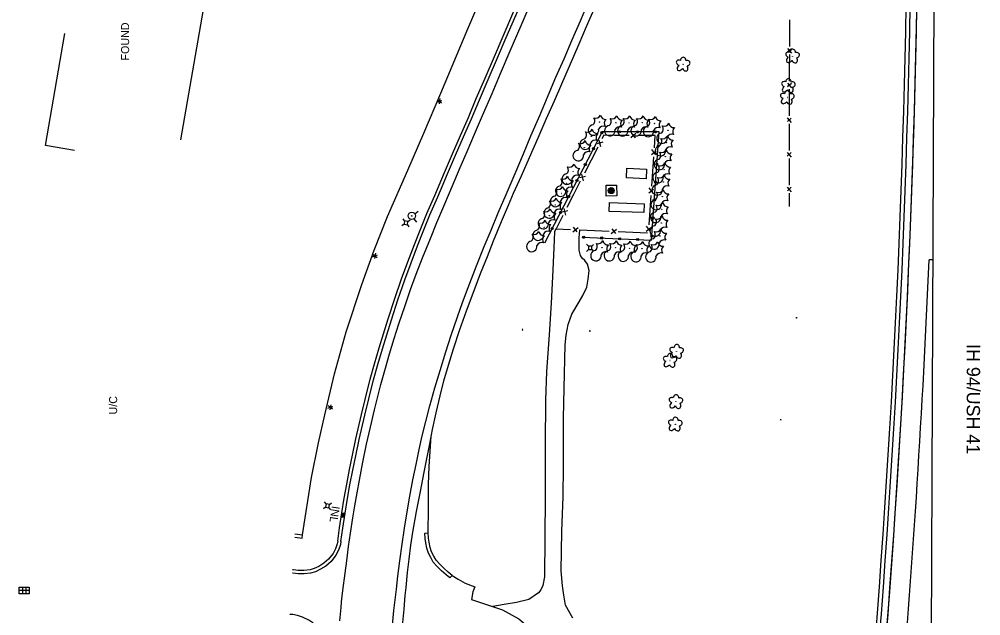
# Model space of a CAD drawing. Extents: x 588843 to 2552415, y 180129 to 269402.
# Drawn here: x 593269 to 593990, y 186692 to 187140 of the extents above; entities that cross this region are included whole.
import ezdxf

# ---------------------------------------------------------------- set-up
doc = ezdxf.new("R2010")
doc.units = 0
for name, color, linetype in [('Default', 7, 'Continuous'), ('E_AREA', 7, 'Continuous'), ('E_BMGRD_P', 7, 'Continuous'), ('E_DRN', 7, 'Continuous'), ('E_DRN_Text', 7, 'Continuous'), ('E_DWY', 7, 'Continuous'), ('E_FEN_P', 7, 'Continuous'), ('E_LAND_Vegetation', 7, 'Continuous'), ('E_LTG', 7, 'Continuous'), ('E_MISCPROP', 7, 'Continuous'), ('E_RDWY', 7, 'Continuous'), ('E_RDWY_C_and_G', 7, 'Continuous'), ('E_RDWY_Gravel', 7, 'Continuous'), ('E_RDWY_Text', 7, 'Continuous'), ('E_UTL_AG_Bold', 7, 'Continuous'), ('E_UTL_WHydrant', 7, 'Continuous'), ('Level 12', 7, 'Continuous'), ('Level 17', 7, 'Continuous'), ('P_ALI_100', 7, 'Continuous'), ('P_RDWY_PavtEdge', 7, 'Continuous'), ('P_RDWY_ShldAgg', 7, 'Continuous'), ('P_RDWY_ShldPaved', 7, 'Continuous')]:
    doc.layers.add(name, color=color, linetype=linetype)

# ---------------------------------------------------------------- blocks, each defined once
blk = doc.blocks.new('CULV2')
at = {"layer": 'E_DRN'}
blk.add_arc((20, 15), 24.6, 216.8699, 323.1301, dxfattribs=at)
blk = doc.blocks.new('DTRE')
at = {"layer": 'Default'}
blk.add_circle((-0.2, 0), 0.183, dxfattribs=at)
for centre, major_axis, ratio in [((-5.9, 0.2), (4.93, -0.12), 0.832022), ((-1.9, 5.3), (1.36, -4.98), 0.782863), ((4.1, 2.7), (-5.27, -2.93), 0.691916), ((-2.5, -5.2), (1.8, 4.86), 0.716896), ((3.5, -3.7), (-5.01, 4.58), 0.560249)]:
    blk.add_ellipse(centre, major_axis=major_axis, ratio=ratio, start_param=1.570796, end_param=4.712389, dxfattribs=at)
blk = doc.blocks.new('POLE')
at = {"layer": 'Default'}
for radius in [4.46, 3.35, 2.23, 1.12]:
    blk.add_circle((0, 0), radius, dxfattribs=at)
blk = doc.blocks.new('PED')
at = {"layer": 'Default'}
for p, q in [((-2.5, 2.5), (-5.3, 5.3)), ((2.5, 2.5), (5.3, 5.3)), ((-2.5, -2.5), (-5.3, -5.3)), ((2.5, -2.5), (5.3, -5.3))]:
    blk.add_line(p, q, dxfattribs=at)
blk.add_lwpolyline([(-2.5, -2.5), (2.5, -2.5), (2.5, 2.5), (-2.5, 2.5)], close=True, dxfattribs=at)
blk = doc.blocks.new('CTRE')
at = {"layer": 'Default'}
blk.add_circle((0, 0), 0.223, dxfattribs=at)
for centre, start, end in [((-12, 9), 280.2067, 5.9716), ((-13.8, -5.9), 340.2113, 65.9762), ((1.8, 14.9), 220.2113, 305.9762), ((13.8, 5.9), 160.2113, 245.9762), ((-1.8, -14.9), 40.2113, 125.9762), ((12, -9), 185.9272, 100.2511)]:
    blk.add_arc(centre, 7.87, start, end, dxfattribs=at)
blk = doc.blocks.new('INLO')
at = {"layer": 'E_DRN'}
for p, q in [((2, -4), (2, 0)), ((4, -4), (4, 0)), ((6, -2), (0, -2))]:
    blk.add_line(p, q, dxfattribs=at)
blk.add_lwpolyline([(0, -4), (6, -4), (6, 0), (0, 0), (0, -4)], close=True, dxfattribs=at)
blk = doc.blocks.new('INLT_13')
at = {"layer": 'E_DRN_Text'}
blk.add_text('INL', height=12, dxfattribs=at).set_placement((-11, -6))
blk = doc.blocks.new('LPOL')
at = {"layer": 'Default'}
for p, q in [((-4, 0), (-1.5, 0)), ((-0.7, 1.3), (-2, 3.5)), ((0.7, 1.3), (2, 3.5)), ((1.5, 0), (4, 0)), ((-2, -3.5), (-0.7, -1.3)), ((2, -3.5), (0.7, -1.3))]:
    blk.add_line(p, q, dxfattribs=at)
for radius in [1.5, 1.5, 1.5, 0.125]:
    blk.add_circle((0, 0), radius, dxfattribs=at)
blk = doc.blocks.new('HYD')
at = {"layer": 'Default'}
for p, q in [((-3.8, 3.8), (-8.3, 8.3)), ((3.8, 3.8), (8.3, 8.3))]:
    blk.add_line(p, q, dxfattribs=at)
for radius in [5.48, 0.42]:
    blk.add_circle((0, 0), radius, dxfattribs=at)

msp = doc.modelspace()

# ---------------------------------------------------------------- linework, layer by layer
at = {"layer": 'E_AREA'}
for points in [[(593724.51, 187027.99), (593739.18, 187027.36), (593738.87, 187020.21), (593724.2, 187020.84), (593724.51, 187027.99)], [(593716.89, 187007.31), (593708.97, 187007.19), (593708.84, 187015.31), (593716.76, 187015.43), (593716.89, 187007.31)], [(593711.42, 187002.24), (593737.36, 187001.29), (593737.12, 186994.74), (593711.18, 186995.69), (593711.42, 187002.24)]]:
    msp.add_lwpolyline(points, close=True, dxfattribs=at)
at = {"layer": 'E_BMGRD_P'}
msp.add_lwpolyline([(593690.97, 186976.29), (593742.88, 186974.07), (593748.63, 187055.26), (593705.99, 187055.31), (593662.75, 186971.82)], dxfattribs=at)
for centre, radius in [((593718.85, 187055.29), 0.786), ((593732.35, 187055.27), 0.786), ((593745.85, 187055.26), 0.786), ((593705.69, 187054.74), 0.786), ((593705.69, 187054.74), 0.396), ((593718.85, 187055.29), 0.396), ((593732.35, 187055.27), 0.396), ((593745.85, 187055.26), 0.396), ((593699.49, 187042.75), 0.786), ((593699.49, 187042.75), 0.396), ((593747.87, 187044.56), 0.786), ((593747.87, 187044.56), 0.396), ((593693.28, 187030.76), 0.786), ((593693.28, 187030.76), 0.396), ((593746.92, 187031.1), 0.786), ((593746.92, 187031.1), 0.396), ((593687.07, 187018.78), 0.786), ((593687.07, 187018.78), 0.396), ((593745.97, 187017.63), 0.786), ((593745.97, 187017.63), 0.396), ((593680.86, 187006.79), 0.786), ((593680.86, 187006.79), 0.396), ((593745.01, 187004.16), 0.786), ((593745.01, 187004.16), 0.396), ((593674.65, 186994.8), 0.786), ((593674.65, 186994.8), 0.396), ((593744.06, 186990.69), 0.786), ((593744.06, 186990.69), 0.396), ((593668.44, 186982.81), 0.786), ((593668.44, 186982.81), 0.396), ((593692.09, 186976.25), 0.786), ((593692.09, 186976.25), 0.396), ((593743.11, 186977.23), 0.786), ((593743.11, 186977.23), 0.396), ((593705.58, 186975.67), 0.786), ((593705.58, 186975.67), 0.396), ((593719.07, 186975.09), 0.786), ((593719.07, 186975.09), 0.396), ((593732.56, 186974.51), 0.786), ((593732.56, 186974.51), 0.396)]:
    msp.add_circle(centre, radius, dxfattribs=at)
at = {"layer": 'E_DRN'}
for p, q in [((593268.89, 186708.85), (593268.89, 186713.85)), ((593268.89, 186713.85), (593276.39, 186713.85)), ((593276.39, 186711.35), (593268.89, 186711.35)), ((593271.39, 186713.85), (593271.39, 186708.85)), ((593273.89, 186713.85), (593273.89, 186708.85)), ((593276.39, 186713.85), (593276.39, 186708.85)), ((593276.39, 186708.85), (593268.89, 186708.85)), ((593272.64, 186708.85), (593272.64, 186708.85))]:
    msp.add_line(p, q, dxfattribs=at)
at = {"layer": 'E_DWY'}
for points in [[(593480.89, 186750.48), (593481.26, 186752.95), (593488.04, 186796.08), (593493.2, 186821.94), (593498.06, 186843.12), (593505.32, 186873.85), (593513.98, 186905.19), (593525.62, 186940.74), (593534.91, 186966.59), (593544.98, 186991.81), (593560.19, 187026.68), (593572.33, 187054.22), (593584.92, 187084.41), (593605.1, 187132.52), (593619.1, 187165.67)], [(593671.3, 186982.53), (593670.29, 186980.24), (593670.03, 186974.37), (593668.98, 186951.69), (593667.75, 186926.78), (593666.08, 186902.94), (593664.08, 186875.44), (593663.42, 186854.07), (593663.11, 186820.89), (593663.28, 186781.57), (593662.96, 186750.8), (593662.63, 186721.59), (593661.42, 186714.93), (593660.04, 186711.76), (593658.18, 186709.48), (593650.92, 186704.51), (593641.7, 186702.39), (593632.52, 186700.81), (593623.84, 186699.16)], [(593683.95, 186690.5), (593678.43, 186700.33), (593677.09, 186707.72), (593676.17, 186714.68), (593675.27, 186726.01), (593675.6, 186755.5), (593676.58, 186781.7), (593676.98, 186804.25), (593677.06, 186840.47), (593677.5, 186862.94), (593678.14, 186895.56), (593678.94, 186902.73), (593680.32, 186910.85), (593683.25, 186918.58), (593688.64, 186927.79), (593691.41, 186932.67), (593694.35, 186938.73), (593695.44, 186944.9), (593696.14, 186951.4), (593694.93, 186956.12), (593692.89, 186958.9), (593691, 186960.54), (593689.58, 186962.53), (593688.71, 186966.53), (593688.65, 186975.78), (593689.13, 186981.75)], [(593575.57, 186754.43), (593575.82, 186772.99), (593575.66, 186790.68), (593576.23, 186804.33), (593577.84, 186826.93)], [(593475.59, 186753.8), (593481.26, 186752.95)], [(593573.07, 186754.32), (593575.57, 186754.43)], [(593591.77, 186720.72), (593588.92, 186723.07), (593585.41, 186726.13), (593582.04, 186729.59), (593579.34, 186732.61), (593577.39, 186735.96), (593575.77, 186739.33), (593574.49, 186742.97), (593573.71, 186747.05), (593573.25, 186750.28), (593573.07, 186754.32)], [(593593.36, 186722.65), (593590.53, 186724.97), (593587.13, 186727.94), (593583.87, 186731.29), (593581.37, 186734.09), (593579.6, 186737.14), (593578.08, 186740.29), (593576.91, 186743.62), (593576.17, 186747.46), (593575.74, 186750.51), (593575.57, 186754.43)], [(593510.11, 186747.96), (593509.65, 186745.72), (593508.26, 186741.54), (593506.3, 186737.71), (593502.67, 186733.03), (593498.74, 186729.65), (593494.81, 186727.16), (593490.91, 186725.34), (593487.38, 186724.34), (593482.43, 186723.86), (593477.94, 186723.88), (593474.12, 186724.29), (593473.71, 186724.36)], [(593507.63, 186748.29), (593507.23, 186746.37), (593505.95, 186742.51), (593504.18, 186739.06), (593500.85, 186734.76), (593497.25, 186731.66), (593493.61, 186729.36), (593490.04, 186727.69), (593486.92, 186726.81), (593482.31, 186726.36), (593478.08, 186726.38), (593474.44, 186726.77), (593473.87, 186726.86)], [(593475.43, 186751.3), (593480.89, 186750.48)], [(593591.77, 186720.72), (593593.36, 186722.65), (593597.85, 186719.78), (593603.23, 186716.86), (593610.4, 186714.07), (593608.97, 186710.3), (593607.96, 186704.52), (593631.13, 186696.7), (593643.55, 186689.9), (593656.66, 186678.88), (593667.04, 186668.23), (593675.78, 186655.81), (593681.53, 186644.73), (593686.85, 186630.53), (593689.52, 186618.63), (593690.53, 186605.83), (593692.03, 186587.19), (593692.36, 186580.89), (593691.77, 186554.75), (593691.75, 186552.08)], [(593500.27, 186636.07), (593499.54, 186644.52), (593498.91, 186653.05), (593498.28, 186664.25), (593497.62, 186671.54), (593496.62, 186675.82), (593495.51, 186679.03), (593493.59, 186682.28), (593491.35, 186685.09), (593488.99, 186687.13), (593486.08, 186689.06), (593481.31, 186691.38), (593477.57, 186692.5), (593474.11, 186693.16), (593471.73, 186693.35)]]:
    msp.add_lwpolyline(points, dxfattribs=at)
at = {"layer": 'E_FEN_P'}
for p, q in [((593844.9, 187117.87), (593847.9, 187114.4)), ((593847.91, 187117.7), (593844.95, 187115.11)), ((593844.81, 187091.87), (593847.81, 187088.4)), ((593847.82, 187091.7), (593844.86, 187089.11)), ((593844.73, 187065.87), (593847.73, 187062.41)), ((593847.74, 187065.71), (593844.78, 187063.11)), ((593703.54, 187049.21), (593704.77, 187044.27)), ((593731.21, 187054.12), (593727.35, 187050.8)), ((593731.01, 187050.78), (593728.14, 187054.07)), ((593706.44, 187047.53), (593702.21, 187046.45)), ((593746.23, 187038.05), (593743.17, 187042.11)), ((593742.91, 187038.46), (593746.38, 187041.11)), ((593844.68, 187039.87), (593847.69, 187036.42)), ((593847.69, 187039.72), (593844.74, 187037.11)), ((593693.32, 187021.82), (593689.09, 187020.74)), ((593690.42, 187023.5), (593691.65, 187018.56)), ((593744.23, 187009.26), (593741.16, 187013.32)), ((593844.73, 187013.87), (593847.74, 187010.42)), ((593847.74, 187013.72), (593844.79, 187011.11)), ((593740.91, 187009.67), (593744.37, 187012.32)), ((593680.2, 186996.11), (593675.97, 186995.03)), ((593677.3, 186997.79), (593678.53, 186992.85)), ((593742.22, 186980.47), (593739.16, 186984.53)), ((593683.94, 186980.43), (593687.92, 186983.6)), ((593684.26, 186983.76), (593687, 186980.37)), ((593712.78, 186979.17), (593716.76, 186982.35)), ((593713.1, 186982.51), (593715.84, 186979.11)), ((593738.9, 186980.87), (593742.37, 186983.53))]:
    msp.add_line(p, q, dxfattribs=at)
for points in [[(593846.38, 187139.25), (593846.34, 187129.32)], [(593846.34, 187129.32), (593846.3, 187119.39)], [(593846.27, 187113.25), (593846.23, 187103.32)], [(593846.23, 187103.32), (593846.23, 187103.23), (593846.2, 187093.39)], [(593846.18, 187087.25), (593846.15, 187077.32)], [(593846.15, 187077.32), (593846.13, 187067.4)], [(593846.11, 187061.25), (593846.08, 187051.32)], [(593715.05, 187052.67), (593707.07, 187052.72), (593705.69, 187050.02)], [(593726.07, 187052.61), (593715.05, 187052.67)], [(593743.91, 187052.5), (593732.89, 187052.57)], [(593745.05, 187043.27), (593745.69, 187052.49), (593743.91, 187052.5)], [(593846.08, 187051.32), (593846.06, 187044.09), (593846.06, 187041.4)], [(593702.59, 187043.94), (593697.58, 187034.12)], [(593743.81, 187025.47), (593744.58, 187036.47)], [(593846.08, 187035.25), (593846.1, 187025.33)], [(593697.58, 187034.12), (593692.57, 187024.31)], [(593743.05, 187014.48), (593743.81, 187025.47)], [(593846.1, 187025.33), (593846.11, 187015.4)], [(593689.47, 187018.23), (593684.46, 187008.41)], [(593684.46, 187008.41), (593679.45, 186998.6)], [(593741.81, 186996.68), (593742.57, 187007.67)], [(593846.13, 187009.25), (593846.15, 186999.33)], [(593676.35, 186992.52), (593671.34, 186982.7)], [(593741.04, 186985.69), (593741.81, 186996.68)], [(593671.3, 186982.53), (593682.31, 186982.05)], [(593689.13, 186981.75), (593700.14, 186981.27)], [(593700.14, 186981.27), (593711.15, 186980.79)], [(593717.97, 186980.49), (593728.98, 186980.01)], [(593728.98, 186980.01), (593739.99, 186979.53)]]:
    msp.add_lwpolyline(points, dxfattribs=at)
at = {"layer": 'E_RDWY'}
for points in [[(593509.33, 186688.56), (593510.2, 186698.64), (593510.56, 186702.87), (593511.44, 186711.18), (593513.18, 186724.3), (593514.44, 186733.63), (593515.85, 186744.38), (593517.23, 186754.4), (593519.12, 186765.79), (593520.6, 186774.75), (593522.26, 186784.57), (593523.97, 186794.02), (593526.48, 186807.55), (593529.32, 186821.01), (593532.12, 186833.72), (593535.29, 186846.74), (593537.4, 186855.7), (593540.1, 186865.7), (593543.44, 186877.95), (593546.52, 186888.77), (593550.04, 186900.36), (593553.47, 186911.27), (593558.12, 186925.07), (593562.25, 186936.99), (593566.48, 186948.69), (593571.28, 186960.75), (593577.11, 186975.44), (593581.98, 186987.27), (593588, 187001.38), (593593.37, 187014.22), (593599.53, 187028.6), (593604.7, 187040.5), (593610.32, 187053.67), (593616.25, 187067.7), (593623.36, 187084.1), (593629.7, 187099.16), (593637.05, 187116.16), (593645.12, 187135.1), (593652.78, 187152.65)], [(593548.58, 186682.57), (593549.68, 186696.2), (593551.65, 186712.39), (593552.82, 186721.92), (593554.29, 186733.42), (593556.09, 186745.95), (593557.82, 186758.07), (593559.7, 186770.23), (593561.79, 186782.14), (593564.06, 186794.32), (593566.36, 186805.82), (593568.61, 186816.96), (593570.98, 186827.42), (593573.62, 186838.07), (593576.7, 186849.89), (593580.47, 186863.31), (593584.46, 186876.42), (593588.69, 186890.37), (593592.73, 186902.69), (593597.41, 186916.59), (593601.26, 186927.33), (593605.39, 186938.5), (593611.73, 186954.85), (593617.49, 186969.22), (593622.66, 186981.65), (593628.03, 186994.56), (593633.84, 187008.22), (593640.6, 187024.14), (593646.87, 187038.95), (593652.56, 187052.44), (593659.08, 187067.58), (593665.44, 187082.57), (593671.08, 187096.36), (593677.34, 187110.15), (593683.22, 187123.79), (593689.69, 187138.53), (593695.28, 187151.59)]]:
    msp.add_lwpolyline(points, dxfattribs=at)
at = {"layer": 'E_RDWY_C_and_G'}
for points in [[(593507.63, 186748.29), (593508.97, 186758.29), (593510.75, 186769.64), (593512.54, 186780.65), (593514.41, 186790.96), (593516.52, 186801.99), (593518.74, 186812.83), (593521.31, 186824.98), (593525.54, 186843.35), (593528.52, 186855.58), (593532.08, 186869.93), (593535.35, 186881.43), (593538.79, 186893.2), (593541.98, 186903.75), (593545.52, 186915.18), (593550.48, 186930.22), (593555.57, 186945.03), (593560.32, 186957.91), (593565.12, 186970.71), (593569.44, 186981.58), (593574.37, 186994.13), (593580.36, 187007.64), (593587.65, 187024.9), (593593.78, 187038.74), (593599.76, 187052.7), (593605.61, 187066.14), (593611.54, 187080.23), (593618.09, 187095.63), (593625.18, 187111.96), (593631.7, 187127.08), (593640.53, 187147.62)], [(593510.11, 186747.96), (593511.45, 186757.93), (593513.22, 186769.25), (593515.01, 186780.23), (593516.87, 186790.5), (593518.98, 186801.5), (593521.19, 186812.33), (593523.75, 186824.44), (593527.98, 186842.77), (593530.94, 186854.98), (593534.49, 186869.28), (593537.75, 186880.74), (593541.19, 186892.49), (593544.37, 186903.02), (593547.91, 186914.42), (593552.85, 186929.42), (593557.92, 186944.2), (593562.67, 186957.04), (593567.45, 186969.81), (593571.77, 186980.66), (593576.68, 186993.17), (593582.66, 187006.65), (593589.95, 187023.91), (593596.07, 187037.74), (593602.05, 187051.71), (593607.91, 187065.15), (593613.85, 187079.26), (593620.39, 187094.64), (593627.48, 187110.97), (593634, 187126.09), (593642.83, 187146.62)]]:
    msp.add_lwpolyline(points, dxfattribs=at)
at = {"layer": 'E_RDWY_Gravel'}
msp.add_lwpolyline([(593556.3, 186684.78), (593557.36, 186697.17), (593558.34, 186707.56), (593558.87, 186713.44), (593560.08, 186724.78), (593561.32, 186734.9), (593562.37, 186745.27), (593564.05, 186754.92), (593566.84, 186770.62), (593569.85, 186785.64), (593572.42, 186800.01), (593576.53, 186819.96), (593578.82, 186832.14), (593581.48, 186844.44), (593584.49, 186857.42), (593587.26, 186868.52), (593590.67, 186880.32), (593594.56, 186892.67), (593599.18, 186907.08), (593604.16, 186920.99), (593609.96, 186936.4), (593614.78, 186948.96), (593619.9, 186961.94), (593624.46, 186973.5), (593630.57, 186988.14), (593635.76, 187000.39), (593639.54, 187009.25), (593645.5, 187022.35), (593651.38, 187036.04), (593657.94, 187050.8), (593664.05, 187064.73), (593670.09, 187078.64), (593675.68, 187091.43), (593681.53, 187104.62), (593688.74, 187121.34), (593694.22, 187134.4), (593700.58, 187149.21)], dxfattribs=at)
at = {"layer": 'Level 12'}
for points in [[(593417.75, 187210.51), (593389.9, 187049.22)], [(593310.3, 187041.33), (593288.69, 187045.06), (593303.2, 187129.12)]]:
    msp.add_lwpolyline(points, dxfattribs=at)
at = {"layer": 'P_ALI_100'}
msp.add_arc((585943.39, 187301.64), 8000, 355.21188, 359.769059, dxfattribs=at)
at = {"layer": 'P_RDWY_PavtEdge'}
for p, q in [((593952.73, 186624.12), (593957.54, 187818.84)), ((593954.08, 186959.28), (593951.08, 186959.29))]:
    msp.add_line(p, q, dxfattribs=at)
for radius, start, end in [(8000, 354.990105, 359.769059), (8015, 355.151389, 357.551942)]:
    msp.add_arc((585943.39, 187301.64), radius, start, end, dxfattribs=at)
at = {"layer": 'P_RDWY_ShldAgg'}
msp.add_arc((585943.39, 187301.64), 7992, 355.213789, 359.769059, dxfattribs=at)
at = {"layer": 'P_RDWY_ShldPaved'}
msp.add_arc((585943.39, 187301.64), 7995, 355.213073, 359.769059, dxfattribs=at)

# ---------------------------------------------------------------- block references
at = {"layer": 'E_DRN'}
for name, p, xscale, yscale, rotation in [('CULV2', (593851.12, 186916.12), 0.02220953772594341, 0.02220953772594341, -4.063647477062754), ('CULV2', (593646.05, 186906.25), 0.03253334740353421, 0.03253334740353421, 88.79875779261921), ('CULV2', (593696.86, 186906.6), 0.03120724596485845, 0.03120724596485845, -93.69079512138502), ('CULV2', (593840.19, 186839.01), 0.022864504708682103, 0.022864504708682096, 164.76251425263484), ('INLO', (593512.87, 186769.16), 0.5, 0.5, -96.91183537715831)]:
    msp.add_blockref(name, p, dxfattribs=dict(at, xscale=xscale, yscale=yscale, rotation=rotation))
at = {"layer": 'E_DRN_Text', "xscale": 0.5, "yscale": 0.5000000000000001, "rotation": -98.91789951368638}
msp.add_blockref('INLT_13', (593505.5, 186769.1), dxfattribs=at)
at = {"layer": 'E_LAND_Vegetation', "xscale": 0.5, "yscale": 0.5, "rotation": -90.39883281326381}
for name, p in [('DTRE', (593848.64, 187111.89)), ('DTRE', (593766.61, 187105.84)), ('DTRE', (593845.53, 187089.83)), ('DTRE', (593844.73, 187080.97)), ('CTRE', (593703.96, 187062.63)), ('CTRE', (593716.2, 187062.14)), ('CTRE', (593725.95, 187062.11)), ('CTRE', (593735.97, 187062.13)), ('CTRE', (593745.13, 187061.56)), ('CTRE', (593697.77, 187052.04)), ('CTRE', (593755.27, 187056.51)), ('CTRE', (593692.52, 187043.48)), ('CTRE', (593754.2, 187047.16)), ('CTRE', (593753.34, 187036.76)), ('CTRE', (593684.18, 187025.81)), ('CTRE', (593752.32, 187026.88)), ('CTRE', (593679.36, 187016.77)), ('CTRE', (593751.72, 187017.76)), ('CTRE', (593675.53, 187009.08)), ('CTRE', (593670.78, 187000.38)), ('CTRE', (593750.99, 187006.77)), ('CTRE', (593750.61, 186997.11)), ('CTRE', (593666.36, 186992.38)), ('CTRE', (593750.26, 186986.93)), ('CTRE', (593662.54, 186983.79)), ('CTRE', (593657.7, 186975.33)), ('CTRE', (593749.32, 186977.23)), ('CTRE', (593705.8, 186968.44)), ('CTRE', (593715.87, 186968.35)), ('CTRE', (593726.37, 186968.04)), ('CTRE', (593735.85, 186967.67)), ('CTRE', (593746.94, 186967.49)), ('DTRE', (593761.68, 186890.39)), ('DTRE', (593756.82, 186883.68)), ('DTRE', (593761.18, 186852.76)), ('DTRE', (593760.74, 186835.83))]:
    msp.add_blockref(name, p, dxfattribs=at)
at = {"layer": 'E_LTG', "xscale": 0.5, "yscale": 0.5000000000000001, "rotation": -98.91789951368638}
for p in [(593583.93, 187078.25), (593535.56, 186962.24), (593502.16, 186848.69)]:
    msp.add_blockref('LPOL', p, dxfattribs=at)
at = {"layer": 'E_MISCPROP', "xscale": 0.5, "yscale": 0.5, "rotation": -90.39883281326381}
msp.add_blockref('POLE', (593712.69, 187011.24), dxfattribs=at)
at = {"layer": 'E_UTL_AG_Bold', "xscale": 0.5}
for p, yscale, rotation in [((593558.86, 186987.05), 0.5000000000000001, -98.91789951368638), ((593696.88, 186968.31), 0.5, -90.39883281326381), ((593500.04, 186774.8), 0.5000000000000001, -98.91789951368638)]:
    msp.add_blockref('PED', p, dxfattribs=dict(at, yscale=yscale, rotation=rotation))
at = {"layer": 'E_UTL_WHydrant', "xscale": 0.5, "yscale": 0.5000000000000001, "rotation": -98.91789951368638}
msp.add_blockref('HYD', (593563.2, 186992.29), dxfattribs=at)

# ---------------------------------------------------------------- texts
at = {"layer": 'E_RDWY_Text'}
msp.add_text('IH 94/USH 41', height=10, rotation=269.84908, dxfattribs=at).set_placement((593979.33, 186896.12))
at = {"layer": 'Level 12'}
msp.add_text('FOUND', height=6, rotation=90, dxfattribs=at).set_placement((593351.26, 187108.85))
at = {"layer": 'Level 17'}
msp.add_text('U/C', height=6, rotation=90, dxfattribs=at).set_placement((593342.29, 186843.34))

doc.saveas('drawing.dxf')
